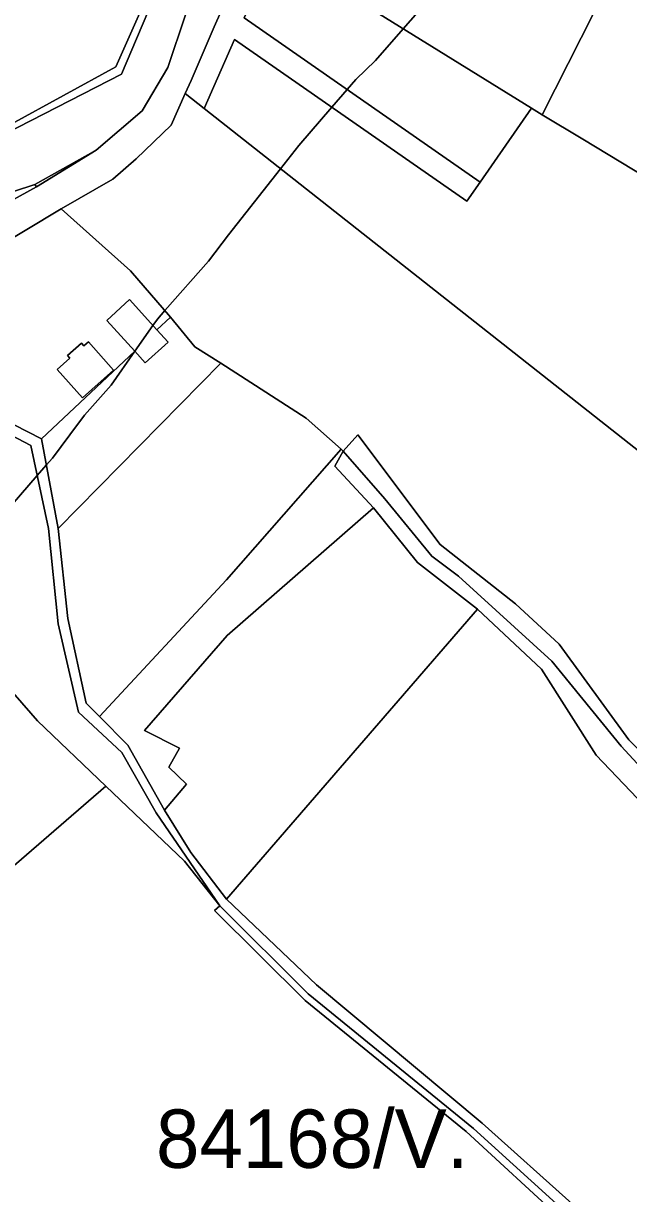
# Model space of a CAD drawing. Extents: x -477304 to -465429, y -1159113 to -1149210.
# Drawn here: x -471294.8 to -471139.2, y -1155161.1 to -1154860.4 of the extents above; entities that cross this region are included whole.
import ezdxf

# ---------------------------------------------------------------- set-up
doc = ezdxf.new("R2010")
doc.units = 0
for name, color, linetype in [('BPEJ_s', 7, 'Continuous'), ('orna_s', 7, 'Continuous'), ('ostatni_s', 7, 'Continuous'), ('PUPFL_s', 7, 'Continuous'), ('trav_porost_s', 7, 'Continuous'), ('voda_s', 7, 'Continuous'), ('zahrada_s', 7, 'Continuous')]:
    doc.layers.add(name, color=color, linetype=linetype)

msp = doc.modelspace()

# ---------------------------------------------------------------- linework, layer by layer
at = {"layer": 'BPEJ_s'}
for points in [[(-471253.99, -1154833.14), (-471270.99, -1154871.6), (-471297.97, -1154886.26), (-471316.27, -1154897.62), (-471316.46, -1154897.74), (-471317.73, -1154897.31), (-471320.92, -1154893.91), (-471324.41, -1154893.33), (-471322.81, -1154892.53), (-471326.73, -1154885.64), (-471330.53, -1154883.53), (-471330.62, -1154883.18), (-471330.91, -1154882.01), (-471322.67, -1154852.48)], [(-471297.97, -1154886.26), (-471270.99, -1154871.6), (-471253.99, -1154833.14)], [(-471180.26, -1154842.49), (-471197.15, -1154861.77), (-471204.27, -1154869.9), (-471209.37, -1154874.79), (-471211.6, -1154877.38), (-471215.55, -1154881.96), (-471224.03, -1154891.79), (-471228.72, -1154897.75), (-471242.09, -1154914.74), (-471247.19, -1154921.53), (-471258.42, -1154934.22), (-471260.36, -1154936.41), (-471261.5, -1154938.03), (-471266.14, -1154944.65), (-471272.26, -1154953.41), (-471279.06, -1154961.06), (-471282.85, -1154966.11), (-471287.35, -1154972.1), (-471288.9, -1154973.9), (-471291.21, -1154976.57), (-471317.52, -1155006.95), (-471318.53, -1155008.26), (-471321.67, -1155012.32)], [(-471317.52, -1155006.95), (-471291.21, -1154976.57), (-471288.9, -1154973.9), (-471287.35, -1154972.1), (-471282.85, -1154966.11), (-471279.06, -1154961.06), (-471272.26, -1154953.41), (-471266.14, -1154944.65), (-471261.5, -1154938.03), (-471260.36, -1154936.41), (-471258.42, -1154934.22), (-471247.19, -1154921.53), (-471242.09, -1154914.74), (-471228.72, -1154897.75), (-471224.03, -1154891.79), (-471215.55, -1154881.96), (-471211.6, -1154877.38), (-471209.37, -1154874.79), (-471204.27, -1154869.9), (-471197.15, -1154861.77), (-471180.26, -1154842.49)]]:
    msp.add_lwpolyline(points, dxfattribs=at)
at = {"layer": 'orna_s'}
for points in [[(-471290.17, -1154967.12), (-471266.15, -1154944.64), (-471263.45, -1154947.6), (-471257.62, -1154942.28), (-471260.48, -1154939.15), (-471256.95, -1154935.93), (-471250.74, -1154943.49), (-471244.03, -1154947.76), (-471285.86, -1154990.22)], [(-471254.65, -1155046.63), (-471263.64, -1155042.12), (-471242.45, -1155017.72), (-471204.8, -1154984.85), (-471193.48, -1154998.9), (-471178.09, -1155010.97), (-471242.6, -1155085.45), (-471251.74, -1155073.45), (-471258.52, -1155062.55), (-471252.84, -1155055.88), (-471257.44, -1155051.52)]]:
    msp.add_lwpolyline(points, close=True, dxfattribs=at)
at = {"layer": 'ostatni_s'}
for points in [[(-471235.43, -1154838.03), (-471245.73, -1154861.27), (-471251.66, -1154875.09), (-471253.19, -1154878.46), (-471256.84, -1154886.52), (-471265.79, -1154895.25), (-471271.8, -1154900.44), (-471285.09, -1154908.08), (-471312.09, -1154924.28)], [(-471514.68, -1155140.72), (-471431.04, -1155055.69), (-471417.85, -1155040.36), (-471362.23, -1154975.69), (-471356.65, -1154971.91), (-471353.13, -1154966.09), (-471350.24, -1154961.31), (-471345.88, -1154946.35), (-471333.31, -1154929.17), (-471325.67, -1154921.28), (-471291.43, -1154902.44), (-471276.05, -1154893), (-471264.22, -1154882.89), (-471257.64, -1154871.71), (-471253.13, -1154858.23)], [(-471154.11, -1155167.06), (-471179.1, -1155144.35), (-471221.6, -1155109.8), (-471244.31, -1155087.18), (-471260.7, -1155063.28), (-471269.51, -1155047.77), (-471280.6, -1155037.37), (-471285.86, -1155014.68), (-471288.34, -1154990.21), (-471292.84, -1154968.86), (-471309.56, -1154960.18), (-471307.96, -1154958.05), (-471290.17, -1154967.12), (-471285.86, -1154990.22), (-471283.35, -1155013.31), (-471278.63, -1155035.12), (-471275.26, -1155038.52), (-471267.96, -1155045.89), (-471258.52, -1155062.55), (-471251.74, -1155073.45), (-471242.6, -1155085.45), (-471219.42, -1155107.5), (-471176.87, -1155143.05), (-471152.93, -1155164.39)], [(-471111.55, -1155078.18), (-471141.12, -1155046.17), (-471158.93, -1155024.27), (-471182.99, -1155002.48), (-471189.84, -1154997.29), (-471201.87, -1154982.54), (-471212.61, -1154970.37), (-471208.85, -1154966.15), (-471187.66, -1154994.28), (-471168.28, -1155009.57), (-471157.06, -1155019.91), (-471139.15, -1155044.53)], [(-471115.77, -1155081.78), (-471147.56, -1155048.43), (-471161.64, -1155026.33), (-471178.09, -1155010.97), (-471193.48, -1154998.9), (-471204.8, -1154984.85), (-471214.7, -1154974.19), (-471212.61, -1154970.37), (-471201.87, -1154982.54), (-471189.84, -1154997.29), (-471182.99, -1155002.48), (-471158.93, -1155024.27), (-471141.12, -1155046.17), (-471111.55, -1155078.18)]]:
    msp.add_lwpolyline(points, dxfattribs=at)
for points in [[(-471291.86, -1154901.81), (-471276.05, -1154893), (-471291.43, -1154902.44)], [(-471260.48, -1154939.15), (-471257.62, -1154942.28), (-471263.45, -1154947.6), (-471266.15, -1154944.64), (-471273.38, -1154936.72), (-471267.55, -1154931.4)], [(-471279.28, -1154943.26), (-471278.09, -1154942.2), (-471271.6, -1154949.5), (-471279.62, -1154956.63), (-471286.11, -1154949.32), (-471282.86, -1154946.43), (-471283.46, -1154945.76), (-471279.88, -1154942.58)]]:
    msp.add_lwpolyline(points, close=True, dxfattribs=at)
at = {"layer": 'PUPFL_s'}
msp.add_lwpolyline([(-471253.41, -1154835.29), (-471269.54, -1154873.43), (-471306.23, -1154892.23), (-471315.76, -1154898.2), (-471326.73, -1154885.64), (-471345.31, -1154873.87), (-471366.73, -1154858.21)], dxfattribs=at)
at = {"layer": 'trav_porost_s'}
for points in [[(-471215.7, -1154810.05), (-471193.1, -1154782.76), (-471187.11, -1154775.6), (-471181.32, -1154765.12), (-471169.69, -1154736.68), (-471164.8, -1154706.11), (-471123.02, -1154706.35), (-471113.7, -1154677.05), (-471109.3, -1154691.37), (-471092.21, -1154746.96), (-471107.78, -1154777.99), (-471161.43, -1154883.93), (-471164.17, -1154882.23), (-471230.27, -1154841.23), (-471235.43, -1154838.03)], [(-471028.11, -1154964.51), (-471151.02, -1154890.17), (-471161.43, -1154883.93), (-471107.78, -1154777.99), (-471064.98, -1154829.61), (-471006.65, -1154894.46), (-470997.42, -1154904.61), (-470995.05, -1154907.22)], [(-471235.43, -1154838.03), (-471230.27, -1154841.23), (-471238.05, -1154858.98), (-471177.38, -1154901.19), (-471180.81, -1154906.13), (-471240.54, -1154864.57), (-471248.31, -1154882.31), (-471253.19, -1154878.46), (-471251.66, -1154875.09), (-471245.73, -1154861.27)], [(-471177.38, -1154901.19), (-471238.05, -1154858.98), (-471230.27, -1154841.23), (-471164.17, -1154882.23)], [(-471164.17, -1154882.23), (-471161.43, -1154883.93), (-471151.02, -1154890.17), (-471028.11, -1154964.51), (-470990.47, -1154986.78), (-470988.27, -1155009.48), (-471033.4, -1155037.07), (-471020.4, -1155061.93), (-471030.46, -1155054), (-471037.77, -1155039.43), (-471044, -1155043.33), (-471159.73, -1154952.12), (-471248.31, -1154882.31), (-471240.54, -1154864.57), (-471180.81, -1154906.13), (-471177.38, -1154901.19)], [(-471044, -1155043.33), (-471047.16, -1155045.3), (-471088.01, -1155090.83), (-471097.95, -1155081.83), (-471111.44, -1155072.78), (-471139.15, -1155044.53), (-471157.06, -1155019.91), (-471168.28, -1155009.57), (-471187.66, -1154994.28), (-471208.85, -1154966.15), (-471212.61, -1154970.37), (-471213.13, -1154969.78), (-471222.12, -1154961.85), (-471244.03, -1154947.76), (-471250.74, -1154943.49), (-471256.95, -1154935.93), (-471267.26, -1154923.95), (-471285.09, -1154908.08), (-471271.8, -1154900.44), (-471265.79, -1154895.25), (-471256.84, -1154886.52), (-471253.19, -1154878.46), (-471248.31, -1154882.31), (-471159.73, -1154952.12)], [(-471333.31, -1154929.17), (-471345.88, -1154946.35), (-471350.24, -1154961.31), (-471353.13, -1154966.09), (-471356.38, -1154963.22), (-471347.06, -1154940.57), (-471328.81, -1154913.86), (-471291.86, -1154901.81), (-471291.43, -1154902.44), (-471325.67, -1154921.28)], [(-471267.55, -1154931.4), (-471273.38, -1154936.72), (-471266.15, -1154944.64), (-471290.17, -1154967.12), (-471307.96, -1154958.05), (-471304.81, -1154954.37), (-471306.2, -1154952.26), (-471297.91, -1154946.12), (-471312.09, -1154924.28), (-471285.09, -1154908.08), (-471267.26, -1154923.95), (-471256.95, -1154935.93), (-471260.48, -1154939.15)], [(-471279.62, -1154956.63), (-471271.6, -1154949.5), (-471278.09, -1154942.2), (-471279.28, -1154943.26), (-471279.88, -1154942.58), (-471283.46, -1154945.76), (-471282.86, -1154946.43), (-471286.11, -1154949.32)], [(-471213.13, -1154969.78), (-471242.57, -1155003.38), (-471275.26, -1155038.52), (-471278.63, -1155035.12), (-471283.35, -1155013.31), (-471285.86, -1154990.22), (-471244.03, -1154947.76), (-471222.12, -1154961.85)], [(-471077.46, -1155111.48), (-471065.29, -1155123.72), (-471033.4, -1155145.45), (-471024.33, -1155153.86), (-471021.6, -1155168.47), (-471026.98, -1155230.79), (-471028.14, -1155244.23), (-471041.18, -1155239.04), (-471074.46, -1155238.48), (-471095.62, -1155209.86), (-471116.11, -1155195.12), (-471152.93, -1155164.39), (-471176.87, -1155143.05), (-471219.42, -1155107.5), (-471242.6, -1155085.45), (-471178.09, -1155010.97), (-471161.64, -1155026.33), (-471147.56, -1155048.43), (-471115.77, -1155081.78), (-471103.13, -1155088.01)], [(-471310.22, -1155017.83), (-471291.19, -1155039.63), (-471273.59, -1155056.44), (-471345.03, -1155118.16), (-471350.96, -1155122.93), (-471382.47, -1155081.21)], [(-471181.01, -1155145.14), (-471222.38, -1155111.48), (-471245.7, -1155088.33), (-471244.31, -1155087.18), (-471221.6, -1155109.8), (-471179.1, -1155144.35), (-471154.11, -1155167.06), (-471100.78, -1155211.06), (-471117.73, -1155200.27), (-471156.07, -1155168.07)]]:
    msp.add_lwpolyline(points, close=True, dxfattribs=at)
for points in [[(-471309.56, -1154960.18), (-471292.84, -1154968.86), (-471288.34, -1154990.21), (-471285.86, -1155014.68), (-471280.6, -1155037.37), (-471269.51, -1155047.77), (-471260.7, -1155063.28), (-471244.31, -1155087.18), (-471253.4, -1155075.71), (-471273.59, -1155056.44), (-471291.19, -1155039.63), (-471310.22, -1155017.83)], [(-471314.08, -1155163.56), (-471319.95, -1155157.93), (-471311.53, -1155149.15), (-471297.72, -1155137.09), (-471301.3, -1155129.59), (-471316.71, -1155136), (-471319.17, -1155132.46), (-471332.8, -1155135.48), (-471337.91, -1155131.03), (-471336.58, -1155126.19), (-471336.9, -1155121.77), (-471340.4, -1155123.35), (-471345.03, -1155118.16), (-471273.59, -1155056.44), (-471253.4, -1155075.71), (-471244.31, -1155087.18), (-471245.7, -1155088.33), (-471222.38, -1155111.48), (-471181.01, -1155145.14), (-471156.07, -1155168.07)]]:
    msp.add_lwpolyline(points, dxfattribs=at)
at = {"layer": 'voda_s'}
for points in [[(-471497.07, -1155109.28), (-471460.8, -1155073.61), (-471442.97, -1155055.73), (-471438.66, -1155050.68), (-471419.35, -1155014.26), (-471408.83, -1154991.74), (-471402.88, -1154982.58), (-471393.84, -1154975.43), (-471379.95, -1154972.26), (-471368.98, -1154969.88), (-471356.86, -1154954.83), (-471352.34, -1154940.74), (-471343.47, -1154922.94), (-471333.28, -1154909.91), (-471315.76, -1154898.2), (-471306.23, -1154892.23), (-471269.54, -1154873.43), (-471253.41, -1154835.29)], [(-471253.13, -1154858.23), (-471257.64, -1154871.71), (-471264.22, -1154882.89), (-471276.05, -1154893), (-471291.86, -1154901.81), (-471328.81, -1154913.86), (-471347.06, -1154940.57), (-471356.38, -1154963.22), (-471362.23, -1154975.69), (-471390.41, -1154980.83), (-471398.67, -1154985.39), (-471408.81, -1155000.15), (-471420.73, -1155024.72), (-471423.23, -1155032.45), (-471431.04, -1155055.69), (-471514.68, -1155140.72)]]:
    msp.add_lwpolyline(points, dxfattribs=at)
at = {"layer": 'zahrada_s'}
msp.add_lwpolyline([(-471213.13, -1154969.78), (-471212.61, -1154970.37), (-471214.7, -1154974.19), (-471204.8, -1154984.85), (-471242.45, -1155017.72), (-471263.64, -1155042.12), (-471254.65, -1155046.63), (-471257.44, -1155051.52), (-471252.84, -1155055.88), (-471258.52, -1155062.55), (-471267.96, -1155045.89), (-471275.26, -1155038.52), (-471242.57, -1155003.38)], close=True, dxfattribs=at)

# ---------------------------------------------------------------- texts
at = {"layer": 'BPEJ_s'}
msp.add_text('84168/V.', height=15, dxfattribs=at).set_placement((-471260.7, -1155154.5))

doc.saveas('drawing.dxf')
